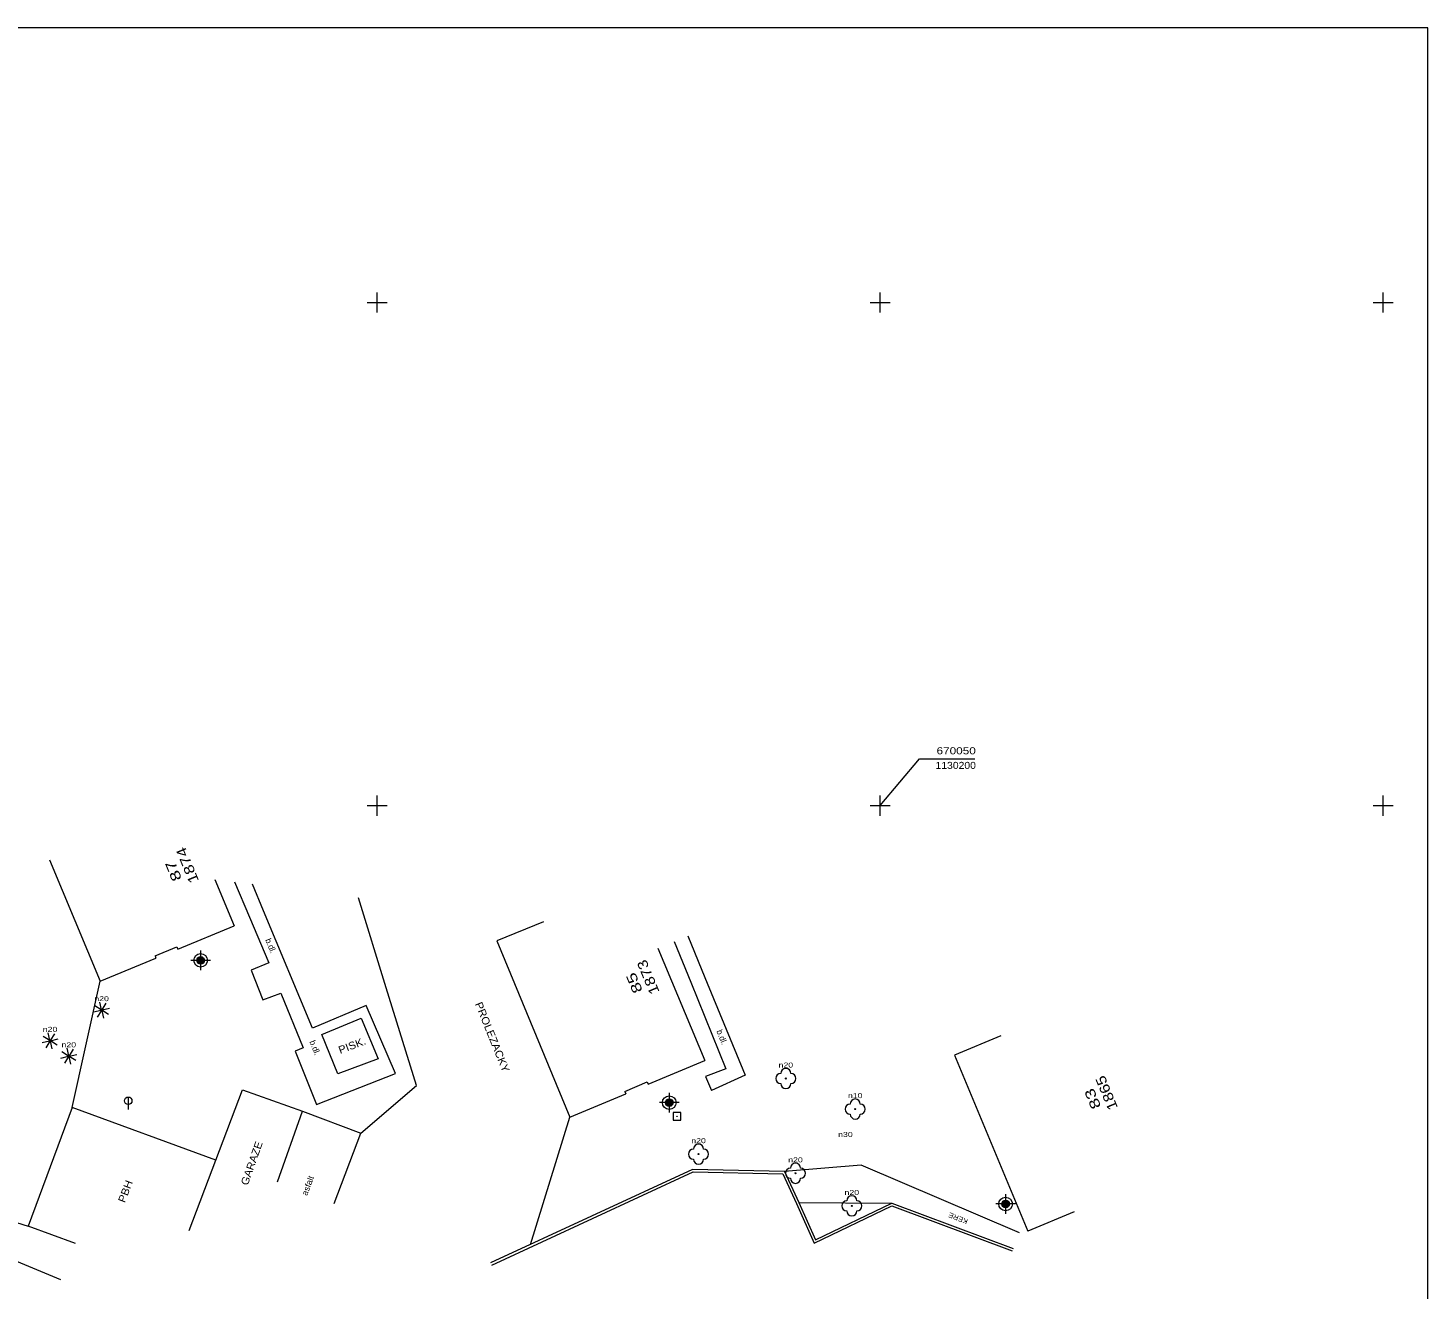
# Model space of a CAD drawing. Extents: x -670514 to -669423, y -1130798 to -1130123.
# Drawn here: x -670134.7 to -669995.6, y -1130248 to -1130122.7 of the extents above; entities that cross this region are included whole.
import ezdxf
from ezdxf.enums import TextEntityAlignment as Align

# ---------------------------------------------------------------- set-up
doc = ezdxf.new("R2010")
doc.units = 0
doc.header["$LTSCALE"] = 0.24
for name, color, linetype, lineweight in [('10', 7, 'Continuous', 13), ('14', 7, 'Continuous', 13), ('22', 7, 'Continuous', 13), ('26', 7, 'Continuous', 13), ('27', 7, 'Continuous', 13), ('35', 7, 'Continuous', 13), ('5', 7, 'Continuous', 13), ('60', 7, 'Continuous', 13), ('61', 7, 'Continuous', 13), ('7', 7, 'Continuous', 13)]:
    doc.layers.add(name, color=color, linetype=linetype, lineweight=lineweight)
for name, color, linetype in [('40', 7, 'Continuous'), ('41', 7, 'Continuous'), ('42', 7, 'Continuous'), ('43', 7, 'Continuous'), ('44', 7, 'Continuous')]:
    doc.layers.add(name, color=color, linetype=linetype)

msp = doc.modelspace()

# ---------------------------------------------------------------- linework, layer by layer
at = {"layer": '10'}
for p, q in [((-670114.162, -1130207.581), (-670112.678, -1130211.1)), ((-670111.272, -1130210.471), (-670112.381, -1130207.81)), ((-670069.13, -1130212.936), (-670067.415, -1130217.082)), ((-670070.482, -1130213.506), (-670068.832, -1130217.558)), ((-670068.832, -1130217.558), (-670065.333, -1130226.15)), ((-670107.397, -1130230.359), (-670101.6, -1130232.561)), ((-670104.252, -1130239.544), (-670101.6, -1130232.561))]:
    msp.add_line(p, q, dxfattribs=at)
for points in [[(-670112.678, -1130211.1), (-670110.766, -1130215.635), (-670112.508, -1130216.337), (-670111.341, -1130219.308), (-670109.568, -1130218.629), (-670107.342, -1130224.059), (-670108.13, -1130224.391)], [(-670108.13, -1130224.391), (-670106.02, -1130229.691), (-670098.162, -1130226.629), (-670101.073, -1130219.879), (-670106.418, -1130222.112), (-670111.272, -1130210.471)], [(-670067.415, -1130217.082), (-670063.403, -1130226.78), (-670066.754, -1130228.298)], [(-670065.333, -1130226.15), (-670067.373, -1130226.932), (-670066.754, -1130228.298)]]:
    msp.add_lwpolyline(points, dxfattribs=at)
msp.add_lwpolyline([(-670105.477, -1130222.751), (-670101.573, -1130221.125), (-670099.902, -1130225.15), (-670103.903, -1130226.65)], close=True, dxfattribs=at)
at = {"layer": '14'}
for p, q in [((-670099.091, -1130218.111), (-670101.846, -1130209.169)), ((-670084.744, -1130243.607), (-670080.848, -1130230.952)), ((-670144.008, -1130238.917), (-670134.666, -1130241.791)), ((-670058.096, -1130239.452), (-670048.853, -1130239.511)), ((-670135.841, -1130245.268), (-670131.45, -1130247.085))]:
    msp.add_line(p, q, dxfattribs=at)
for points in [[(-670101.6, -1130232.561), (-670096.097, -1130227.828), (-670099.091, -1130218.111)], [(-670036.149, -1130242.476), (-670051.889, -1130235.723), (-670059.497, -1130236.35)]]:
    msp.add_lwpolyline(points, dxfattribs=at)
at = {"layer": '22'}
for p, q in [((-670127.411, -1130220.299), (-670128.067, -1130219.885)), ((-670127.385, -1130220.279), (-670127.557, -1130219.525)), ((-670126.943, -1130219.629), (-670127.357, -1130220.285)), ((-670127.337, -1130220.311), (-670126.583, -1130220.139)), ((-670128.171, -1130220.499), (-670127.417, -1130220.327)), ((-670127.397, -1130220.353), (-670127.811, -1130221.009)), ((-670127.369, -1130220.359), (-670127.197, -1130221.113)), ((-670126.687, -1130220.753), (-670127.343, -1130220.339)), ((-670132.535, -1130223.351), (-670133.191, -1130222.937)), ((-670132.509, -1130223.331), (-670132.681, -1130222.577)), ((-670132.067, -1130222.681), (-670132.481, -1130223.337)), ((-670133.295, -1130223.551), (-670132.541, -1130223.379)), ((-670132.521, -1130223.405), (-670132.935, -1130224.061)), ((-670132.493, -1130223.411), (-670132.321, -1130224.165)), ((-670131.811, -1130223.805), (-670132.467, -1130223.391)), ((-670132.461, -1130223.363), (-670131.707, -1130223.191)), ((-670130.645, -1130224.867), (-670130.817, -1130224.113)), ((-670130.203, -1130224.217), (-670130.617, -1130224.873)), ((-670131.431, -1130225.087), (-670130.677, -1130224.915)), ((-670130.671, -1130224.887), (-670131.327, -1130224.473)), ((-670130.657, -1130224.941), (-670131.071, -1130225.597)), ((-670130.629, -1130224.947), (-670130.457, -1130225.701)), ((-670129.947, -1130225.341), (-670130.603, -1130224.927)), ((-670130.597, -1130224.899), (-670129.843, -1130224.727))]:
    msp.add_line(p, q, dxfattribs=at)
for centre, radius in [((-670127.377, -1130220.319), 0.04), ((-670132.501, -1130223.371), 0.04), ((-670130.637, -1130224.907), 0.04), ((-670059.375, -1130227.12), 0.05), ((-670052.477, -1130230.157), 0.05), ((-670068.049, -1130234.635), 0.05), ((-670058.415, -1130236.542), 0.05), ((-670052.817, -1130239.784), 0.05)]:
    msp.add_circle(centre, radius, dxfattribs=at)
for centre, start, end in [((-670059.875, -1130227.12), 90, 270), ((-670059.375, -1130226.62), 0, 180), ((-670058.875, -1130227.12), 270, 90), ((-670059.375, -1130227.62), 180, 0), ((-670052.977, -1130230.157), 90, 270), ((-670052.477, -1130229.657), 0, 180), ((-670051.977, -1130230.157), 270, 90), ((-670052.477, -1130230.657), 180, 0), ((-670068.049, -1130234.135), 0, 180), ((-670068.549, -1130234.635), 90, 270), ((-670068.049, -1130235.135), 180, 0), ((-670067.549, -1130234.635), 270, 90), ((-670058.915, -1130236.542), 90, 270), ((-670058.415, -1130236.042), 0, 180), ((-670057.915, -1130236.542), 270, 90), ((-670058.415, -1130237.042), 180, 0), ((-670053.317, -1130239.784), 90, 270), ((-670052.817, -1130239.284), 0, 180), ((-670052.317, -1130239.784), 270, 90), ((-670052.817, -1130240.284), 180, 0)]:
    msp.add_arc(centre, 0.5, start, end, dxfattribs=at)
at = {"layer": '26'}
msp.add_lwpolyline([(-670070.566, -1130231.256), (-670069.816, -1130231.256), (-670069.816, -1130230.506), (-670070.566, -1130230.506)], close=True, dxfattribs=at)
msp.add_circle((-670070.1909, -1130230.881), 0.02, dxfattribs=at)
at = {"layer": '27'}
msp.add_line((-670124.735, -1130228.962), (-670124.735, -1130230.212), dxfattribs=at)
msp.add_circle((-670124.7346, -1130229.3371), 0.375, dxfattribs=at)
at = {"layer": '35'}
for p, q in [((-670117.536, -1130214.401), (-670117.536, -1130215.001)), ((-670117.911, -1130215.376), (-670118.511, -1130215.376)), ((-670117.911, -1130215.376), (-670117.161, -1130215.376)), ((-670117.899, -1130215.282), (-670117.173, -1130215.282)), ((-670117.899, -1130215.47), (-670117.173, -1130215.47)), ((-670117.861, -1130215.189), (-670117.211, -1130215.189)), ((-670117.861, -1130215.563), (-670117.211, -1130215.563)), ((-670117.817, -1130215.128), (-670117.817, -1130215.624)), ((-670117.784, -1130215.095), (-670117.288, -1130215.095)), ((-670117.784, -1130215.657), (-670117.288, -1130215.657)), ((-670117.724, -1130215.051), (-670117.724, -1130215.701)), ((-670117.63, -1130215.013), (-670117.63, -1130215.739)), ((-670117.536, -1130215.001), (-670117.536, -1130215.751)), ((-670117.536, -1130215.751), (-670117.536, -1130216.351)), ((-670117.442, -1130215.013), (-670117.442, -1130215.739)), ((-670117.348, -1130215.051), (-670117.348, -1130215.701)), ((-670117.255, -1130215.128), (-670117.255, -1130215.624)), ((-670116.561, -1130215.376), (-670117.161, -1130215.376)), ((-670070.966, -1130228.541), (-670070.966, -1130229.141)), ((-670071.341, -1130229.516), (-670071.941, -1130229.516)), ((-670071.341, -1130229.516), (-670070.591, -1130229.516)), ((-670071.329, -1130229.422), (-670070.603, -1130229.422)), ((-670071.329, -1130229.61), (-670070.603, -1130229.61)), ((-670071.291, -1130229.329), (-670070.641, -1130229.329)), ((-670071.291, -1130229.703), (-670070.641, -1130229.703)), ((-670071.247, -1130229.268), (-670071.247, -1130229.764)), ((-670071.214, -1130229.235), (-670070.718, -1130229.235)), ((-670071.214, -1130229.797), (-670070.718, -1130229.797)), ((-670071.154, -1130229.191), (-670071.154, -1130229.841)), ((-670071.06, -1130229.153), (-670071.06, -1130229.879)), ((-670070.966, -1130229.141), (-670070.966, -1130229.891)), ((-670070.966, -1130229.891), (-670070.966, -1130230.491)), ((-670070.872, -1130229.153), (-670070.872, -1130229.879)), ((-670070.778, -1130229.191), (-670070.778, -1130229.841)), ((-670070.685, -1130229.268), (-670070.685, -1130229.764)), ((-670069.991, -1130229.516), (-670070.591, -1130229.516)), ((-670037.912, -1130239.592), (-670038.512, -1130239.592)), ((-670037.912, -1130239.592), (-670037.162, -1130239.592)), ((-670037.9, -1130239.498), (-670037.174, -1130239.498)), ((-670037.862, -1130239.405), (-670037.212, -1130239.405)), ((-670037.818, -1130239.344), (-670037.818, -1130239.84)), ((-670037.785, -1130239.311), (-670037.289, -1130239.311)), ((-670037.725, -1130239.267), (-670037.725, -1130239.917)), ((-670037.631, -1130239.229), (-670037.631, -1130239.955)), ((-670037.537, -1130238.617), (-670037.537, -1130239.217)), ((-670037.537, -1130239.217), (-670037.537, -1130239.967)), ((-670037.443, -1130239.229), (-670037.443, -1130239.955)), ((-670037.349, -1130239.267), (-670037.349, -1130239.917)), ((-670037.256, -1130239.344), (-670037.256, -1130239.84)), ((-670036.562, -1130239.592), (-670037.162, -1130239.592)), ((-670037.9, -1130239.686), (-670037.174, -1130239.686)), ((-670037.862, -1130239.779), (-670037.212, -1130239.779)), ((-670037.785, -1130239.873), (-670037.289, -1130239.873)), ((-670037.537, -1130239.967), (-670037.537, -1130240.567))]:
    msp.add_line(p, q, dxfattribs=at)
for centre, radius in [((-670117.536, -1130215.376), 0.675), ((-670117.536, -1130215.376), 0.375), ((-670070.966, -1130229.516), 0.675), ((-670070.966, -1130229.516), 0.375), ((-670037.537, -1130239.592), 0.675), ((-670037.537, -1130239.592), 0.375)]:
    msp.add_circle(centre, radius, dxfattribs=at)
at = {"layer": '5'}
for p, q in [((-670132.546, -1130205.388), (-670127.519, -1130217.462)), ((-670116.114, -1130207.329), (-670114.21, -1130211.952)), ((-670083.469, -1130211.539), (-670088.089, -1130213.451)), ((-670119.813, -1130214.259), (-670114.21, -1130211.952)), ((-670122.069, -1130214.921), (-670119.908, -1130214.028)), ((-670119.908, -1130214.028), (-670119.813, -1130214.259)), ((-670088.089, -1130213.451), (-670080.848, -1130230.952)), ((-670072.099, -1130214.164), (-670067.429, -1130225.324)), ((-670127.519, -1130217.462), (-670121.973, -1130215.152)), ((-670122.069, -1130214.921), (-670121.973, -1130215.152)), ((-670037.996, -1130222.871), (-670042.612, -1130224.794)), ((-670073.05, -1130227.676), (-670067.429, -1130225.324)), ((-670042.612, -1130224.794), (-670035.325, -1130242.286)), ((-670075.361, -1130228.41), (-670073.147, -1130227.445)), ((-670075.361, -1130228.41), (-670075.265, -1130228.641)), ((-670073.147, -1130227.445), (-670073.05, -1130227.676)), ((-670080.848, -1130230.952), (-670075.265, -1130228.641)), ((-670130.31, -1130229.995), (-670134.666, -1130241.791)), ((-670116.023, -1130235.235), (-670130.31, -1130229.995)), ((-670109.888, -1130237.404), (-670107.397, -1130230.359)), ((-670118.662, -1130242.228), (-670116.023, -1130235.235)), ((-670030.709, -1130240.363), (-670035.325, -1130242.286)), ((-670129.976, -1130243.523), (-670134.666, -1130241.791))]:
    msp.add_line(p, q, dxfattribs=at)
msp.add_lwpolyline([(-670116.023, -1130235.235), (-670113.384, -1130228.242), (-670107.397, -1130230.359)], dxfattribs=at)
at = {"layer": '60'}
msp.add_lwpolyline([(-670405.553, -1130409.706), (-669995.553, -1130409.706), (-669995.553, -1130122.706), (-670405.553, -1130122.706)], close=True, dxfattribs=at)
at = {"layer": '61'}
for p, q in [((-670100, -1130151), (-670100, -1130149)), ((-670050, -1130151), (-670050, -1130149)), ((-670000, -1130151), (-670000, -1130149)), ((-670101, -1130150), (-670099, -1130150)), ((-670051, -1130150), (-670049, -1130150)), ((-670001, -1130150), (-669999, -1130150)), ((-670100, -1130201), (-670100, -1130199)), ((-670050, -1130201), (-670050, -1130199)), ((-670000, -1130201), (-670000, -1130199)), ((-670101, -1130200), (-670099, -1130200)), ((-670051, -1130200), (-670049, -1130200)), ((-670001, -1130200), (-669999, -1130200))]:
    msp.add_line(p, q, dxfattribs=at)
msp.add_lwpolyline([(-670050, -1130200), (-670046.1, -1130195.336), (-670040.6, -1130195.336)], dxfattribs=at)
at = {"layer": '7'}
msp.add_line((-670130.31, -1130229.995), (-670127.519, -1130217.462), dxfattribs=at)
for points in [[(-670059.497, -1130236.35), (-670068.641, -1130236.159), (-670088.716, -1130245.444)], [(-670088.611, -1130245.67), (-670068.588, -1130236.409), (-670059.659, -1130236.596), (-670058.323, -1130239.554), (-670056.565, -1130243.495), (-670048.84, -1130239.782), (-670036.881, -1130244.235)], [(-670059.497, -1130236.35), (-670058.096, -1130239.452), (-670056.442, -1130243.159), (-670048.853, -1130239.511), (-670036.794, -1130244.001)]]:
    msp.add_lwpolyline(points, dxfattribs=at)

# ---------------------------------------------------------------- texts
at = {"layer": '22', "width": 1.3}
for s, p in [('n20', (-670127.3775, -1130219.433)), ('n20', (-670132.5015, -1130222.485)), ('n20', (-670130.6375, -1130224.021)), ('n20', (-670059.3745, -1130226.034)), ('n10', (-670052.4775, -1130229.071)), ('n30', (-670053.4525, -1130232.933)), ('n20', (-670068.0485, -1130233.549)), ('n20', (-670058.4145, -1130235.456)), ('n20', (-670052.8165, -1130238.698))]:
    msp.add_text(s, height=0.499, dxfattribs=at).set_placement(p, align=Align.CENTER)
at = {"layer": '22', "width": 1.1}
msp.add_text('KERE', height=0.499, rotation=158.295, dxfattribs=at).set_placement((-670042.1582, -1130240.7791), align=Align.CENTER)
at = {"layer": '40'}
for rotation, p in [(292.861, (-670110.841, -1130214.051)), (292.158, (-670065.9995, -1130223.1164)), (291.708, (-670106.4474, -1130224.1685))]:
    msp.add_text('b.dl.', height=0.6, rotation=rotation, dxfattribs=at).set_placement(p, align=Align.CENTER)
at = {"layer": '40', "width": 1.05}
msp.add_text('asfalt', height=0.6, rotation=69.204, dxfattribs=at).set_placement((-670106.6039, -1130237.8745), align=Align.CENTER)
at = {"layer": '41', "width": 1.1}
for s, rotation, p in [('GARAZE', 70.527, (-670112.1069, -1130235.667)), ('PBH', 69.325, (-670124.6639, -1130238.4689))]:
    msp.add_text(s, height=0.75, rotation=rotation, dxfattribs=at).set_placement(p, align=Align.CENTER)
at = {"layer": '42', "width": 1.1}
for s, rotation, p in [('PROLEZACKY', 292.044, (-670088.8937, -1130223.1393)), ('PISK.', 20.551, (-670102.3486, -1130224.1889))]:
    msp.add_text(s, height=0.75, rotation=rotation, dxfattribs=at).set_placement(p, align=Align.CENTER)
at = {"layer": '43'}
for s, rotation, width, p in [('1874', 112.384, 1.25, (-670118.392, -1130205.7374)), ('1873', 112.707, 1.2, (-670072.5978, -1130216.857)), ('1865', 112.617, 1.2, (-670027.0395, -1130228.3713))]:
    msp.add_text(s, height=1, rotation=rotation, dxfattribs=dict(at, width=width)).set_placement(p, align=Align.CENTER)
at = {"layer": '44', "width": 1.4}
for s, rotation, p in [('87', 112.384, (-670119.7792, -1130206.3069)), ('85', 112.707, (-670073.9818, -1130217.4355)), ('83', 112.617, (-670028.423, -1130228.9478))]:
    msp.add_text(s, height=1, rotation=rotation, dxfattribs=at).set_placement(p, align=Align.CENTER)
at = {"layer": '61'}
for s, width, p in [('670050', 1.25, (-670042.4465, -1130194.895)), ('1130200', 1.1, (-670042.491, -1130196.349))]:
    msp.add_text(s, height=0.7, dxfattribs=dict(at, width=width)).set_placement(p, align=Align.CENTER)

doc.saveas('drawing.dxf')
